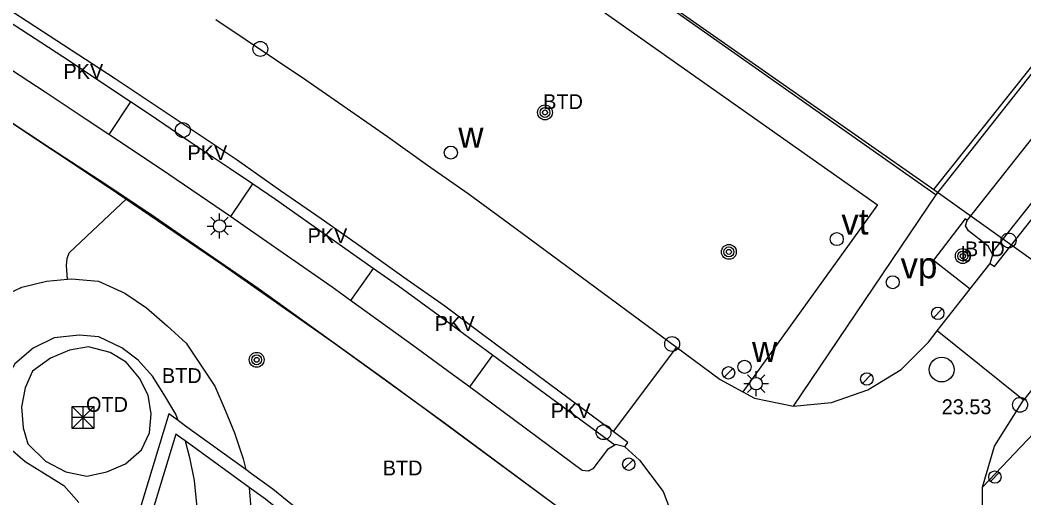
# Model space of a CAD drawing. Extents: x 198240 to 198429, y 356553 to 356721.
# Drawn here: x 198349.04 to 198389.56, y 356639.08 to 356658.34 of the extents above; entities that cross this region are included whole.
import ezdxf

# ---------------------------------------------------------------- set-up
doc = ezdxf.new("R2010")
doc.units = 0
for name, color, linetype in [('Afsluitpaal', 7, 'Continuous'), ('begroeid terreindeel kenmerkpunt', 7, 'Continuous'), ('Benzineput_olieput', 7, 'Continuous'), ('BOOM', 7, 'Continuous'), ('cultuurscheiding geen IMGeo', 7, 'Continuous'), ('grens individueel parkeervak', 7, 'Continuous'), ('Grens maaiveld', 7, 'Continuous'), ('heg geen IMGeo', 7, 'Continuous'), ('Hoogtepunt', 7, 'Continuous'), ('identificerend kenmerkpunt parkeervak', 7, 'Continuous'), ('Inspectieput_rioolput', 7, 'Continuous'), ('kant verharding', 7, 'Continuous'), ('kolk', 7, 'Continuous'), ('LICHTMAST', 7, 'Continuous'), ('onbegroeid terreindeel kenmerkpunt', 7, 'Continuous'), ('perceelsgrens_definitief', 7, 'Continuous'), ('Speelvoorziening', 7, 'Continuous'), ('Verklikker transportleiding', 7, 'Continuous'), ('vlakafsluiter', 7, 'Continuous'), ('waterleidingput', 7, 'Continuous'), ('weginrichtingselement', 7, 'Continuous'), ('weginrichtingselement lijn', 7, 'Continuous')]:
    doc.layers.add(name, color=color, linetype=linetype)

msp = doc.modelspace()

# ---------------------------------------------------------------- linework, layer by layer
at = {"layer": 'Afsluitpaal'}
for p, q in [((198386.253, 356646.699), (198385.903, 356646.342)), ((198377.809, 356644.299), (198377.459, 356643.942)), ((198383.391, 356644.049), (198383.041, 356643.692)), ((198373.781, 356640.617), (198373.431, 356640.26)), ((198388.561, 356640.097), (198388.211, 356639.74))]:
    msp.add_line(p, q, dxfattribs=at)
for centre in [(198386.08, 356646.519), (198377.636, 356644.119), (198383.218, 356643.869), (198373.608, 356640.437), (198388.388, 356639.917)]:
    msp.add_circle(centre, 0.25, dxfattribs=at)
at = {"layer": 'Benzineput_olieput'}
msp.add_circle((198384.261, 356647.771), 0.263, dxfattribs=at)
msp.add_circle((198384.261, 356647.771), 0.263, dxfattribs=at)
at = {"layer": 'BOOM'}
for centre, radius in [((198370.229, 356654.619), 0.3), ((198370.229, 356654.619), 0.2), ((198370.229, 356654.619), 0.1), ((198377.651, 356648.996), 0.3), ((198377.651, 356648.996), 0.2), ((198377.651, 356648.996), 0.1), ((198387.091, 356648.827), 0.3), ((198387.091, 356648.827), 0.2), ((198387.091, 356648.827), 0.1), ((198358.592, 356644.644), 0.3), ((198358.592, 356644.644), 0.2), ((198358.592, 356644.644), 0.1)]:
    msp.add_circle(centre, radius, dxfattribs=at)
at = {"layer": 'cultuurscheiding geen IMGeo'}
msp.add_lwpolyline([(198349.362, 356641.262), (198350.072, 356640.553), (198350.887, 356640.13), (198351.744, 356639.959), (198352.552, 356640.124), (198353.299, 356640.446), (198353.945, 356641.014), (198354.262, 356641.702), (198354.336, 356642.469), (198354.214, 356643.222), (198353.859, 356643.908), (198353.327, 356644.551), (198352.681, 356644.933), (198351.806, 356645.169), (198351.039, 356645.03), (198350.27, 356644.717), (198349.542, 356644.191), (198349.252, 356643.515), (198349.096, 356642.75), (198349.164, 356641.9), (198349.362, 356641.262)], dxfattribs=at)
at = {"layer": 'grens individueel parkeervak'}
for p, q in [((198353.497, 356655.053), (198352.624, 356653.732)), ((198358.424, 356651.737), (198357.53, 356650.42)), ((198363.297, 356648.326), (198362.385, 356647.033)), ((198368.112, 356644.829), (198367.176, 356643.555))]:
    msp.add_line(p, q, dxfattribs=at)
at = {"layer": 'Grens maaiveld'}
for p, q in [((198389.546, 356643.023), (198386.058, 356645.809)), ((198375.533, 356645.157), (198372.981, 356641.75)), ((198355.726, 356641.973), (198355.423, 356642.194)), ((198358.152, 356640.215), (198355.726, 356641.973)), ((198355.703, 356641.372), (198355.432, 356641.569)), ((198358.285, 356639.502), (198355.703, 356641.372)), ((198358.39, 356640.042), (198358.152, 356640.215))]:
    msp.add_line(p, q, dxfattribs=at)
for points in [[(198372.981, 356641.75), (198367.706, 356645.661), (198366.187, 356646.802), (198364.538, 356647.958), (198362.833, 356649.176), (198361.195, 356650.33), (198359.548, 356651.463), (198357.799, 356652.691), (198352.878, 356655.977), (198347.848, 356659.26), (198346.187, 356660.353), (198344.459, 356661.463), (198342.759, 356662.483), (198340.988, 356663.592), (198339.269, 356664.603), (198335.834, 356666.664), (198332.346, 356668.725), (198327.175, 356671.678), (198323.573, 356673.677), (198320.05, 356675.592), (198317.553, 356676.932)], [(198388.2, 356648.534), (198388.372, 356648.404), (198394.89, 356656.659), (198396.809, 356659.133), (198396.637, 356659.256)], [(198349.119, 356647.571), (198350.115, 356647.818), (198350.964, 356647.896)], [(198350.964, 356647.896), (198351.115, 356647.91), (198352.21, 356647.812), (198353.267, 356647.331), (198354.149, 356646.74), (198354.975, 356646.017), (198355.744, 356645.322), (198356.902, 356643.575), (198357.326, 356642.62), (198357.697, 356641.7), (198358.046, 356640.645), (198358.152, 356640.215)], [(198347.617, 356639.006), (198347.475, 356639.042), (198346.828, 356639.275), (198346.287, 356639.639), (198345.935, 356640.096), (198345.691, 356640.614), (198345.65, 356641.176), (198345.843, 356643.252), (198346.007, 356643.901), (198346.27, 356644.596), (198346.627, 356645.198), (198347.603, 356646.563), (198348.274, 356647.167), (198349.119, 356647.571)], [(198355.423, 356642.194), (198355.328, 356642.451), (198354.846, 356643.261), (198354.393, 356643.982), (198353.807, 356644.635), (198353.149, 356645.122), (198352.227, 356645.566), (198351.429, 356645.638), (198350.422, 356645.527), (198349.57, 356645.114), (198348.838, 356644.484), (198348.416, 356643.729), (198348.214, 356642.804), (198348.101, 356641.911), (198348.543, 356641.156), (198349.256, 356640.546), (198350.809, 356639.574), (198351.421, 356638.896)], [(198349.362, 356641.262), (198350.072, 356640.553), (198350.887, 356640.13), (198351.744, 356639.959), (198352.552, 356640.124), (198353.299, 356640.446), (198353.945, 356641.014), (198354.262, 356641.702), (198354.336, 356642.469), (198354.214, 356643.222), (198353.859, 356643.908), (198353.327, 356644.551), (198352.681, 356644.933), (198351.806, 356645.169), (198351.039, 356645.03), (198350.27, 356644.717), (198349.542, 356644.191), (198349.252, 356643.515), (198349.096, 356642.75), (198349.164, 356641.9), (198349.362, 356641.262)], [(198355.423, 356642.194), (198355.054, 356642.463), (198353.086, 356636)], [(198355.432, 356641.569), (198355.328, 356641.645), (198353.564, 356635.854)], [(198373.454, 356641.134), (198373.573, 356641.311), (198372.981, 356641.75)], [(198355.703, 356641.372), (198355.885, 356640.7), (198356.064, 356639.773), (198356.166, 356638.829), (198356.197, 356637.88), (198356.155, 356637.553)], [(198360.838, 356638.137), (198359.247, 356639.427), (198358.39, 356640.042)], [(198358.285, 356639.502), (198358.345, 356638.809), (198358.369, 356637.843), (198358.247, 356636.985), (198358.109, 356636.322)], [(198360.315, 356637.918), (198358.943, 356639.029), (198358.285, 356639.502)]]:
    msp.add_lwpolyline(points, dxfattribs=at)
at = {"layer": 'heg geen IMGeo'}
for points in [[(198360.838, 356638.137), (198359.247, 356639.427), (198358.39, 356640.042)], [(198360.315, 356637.918), (198358.943, 356639.029), (198358.285, 356639.502)]]:
    msp.add_lwpolyline(points, dxfattribs=at)
at = {"layer": 'Inspectieput_rioolput'}
msp.add_circle((198386.24, 356644.252), 0.5, dxfattribs=at)
at = {"layer": 'kant verharding'}
for p, q in [((198387.265, 356650.262), (198391.017, 356655.011)), ((198392.286, 356654.04), (198388.264, 356648.959)), ((198353.348, 356651.154), (198352.51, 356651.714)), ((198387.388, 356647.501), (198388.2, 356648.534)), ((198386.058, 356645.809), (198387.388, 356647.501)), ((198373.044, 356641.207), (198368.112, 356644.829))]:
    msp.add_line(p, q, dxfattribs=at)
for points in [[(198352.51, 356651.714), (198350.276, 356653.164), (198348.4, 356654.399), (198343.742, 356657.419), (198341.543, 356658.825), (198339.43, 356660.09), (198337.442, 356661.338), (198333.99, 356663.38), (198332.34, 356664.377), (198330.533, 356665.43), (198328.787, 356666.422), (198324.464, 356668.899), (198322.677, 356669.861), (198318.431, 356672.186), (198316.529, 356673.188), (198314.814, 356674.063)], [(198360.197, 356669.267), (198362.576, 356667.673), (198364.582, 356666.298), (198366.655, 356664.862), (198368.765, 356663.429), (198386.018, 356651.295)], [(198361.758, 356666.189), (198372.084, 356659.041), (198383.655, 356650.892), (198378.215, 356643.352)], [(198404.26, 356661.992), (198403.096, 356660.379), (198401.903, 356658.745), (198399.503, 356655.567), (198397.022, 356652.414), (198395.783, 356650.82), (198394.543, 356649.264), (198393.305, 356647.686), (198392.04, 356646.144), (198390.785, 356644.559), (198389.546, 356643.023)], [(198353.497, 356655.053), (198352.664, 356655.604), (198351.039, 356656.691), (198348.537, 356658.312)], [(198356.948, 356658.373), (198360.581, 356655.932), (198363.871, 356653.655), (198365.49, 356652.496), (198367.13, 356651.344), (198368.743, 356650.174), (198375.533, 356645.157)], [(198386.018, 356651.295), (198391.518, 356658.255)], [(198352.624, 356653.732), (198351.715, 356654.33), (198350.052, 356655.44), (198347.676, 356656.983)], [(198358.424, 356651.737), (198357.528, 356652.345), (198355.914, 356653.42), (198354.291, 356654.528), (198353.497, 356655.053)], [(198357.53, 356650.42), (198355.048, 356652.112), (198353.386, 356653.231), (198352.624, 356653.732)], [(198363.297, 356648.326), (198359.359, 356651.103), (198358.424, 356651.737)], [(198350.964, 356647.896), (198350.918, 356648.442), (198350.938, 356648.733), (198351.026, 356648.955), (198353.348, 356651.154)], [(198355.686, 356649.56), (198354.494, 356650.389), (198353.348, 356651.154)], [(198362.385, 356647.033), (198361.638, 356647.571), (198358.345, 356649.864), (198357.53, 356650.42)], [(198387.265, 356650.262), (198387.19, 356650.335), (198385.905, 356648.667), (198387.388, 356647.501)], [(198388.264, 356648.959), (198388.115, 356649.222), (198387.326, 356649.845), (198387.2, 356650.042), (198387.265, 356650.262)], [(198375.379, 356635.292), (198365.453, 356642.617), (198363.834, 356643.796), (198358.657, 356647.515), (198356.63, 356648.904), (198355.686, 356649.56)], [(198388.2, 356648.534), (198388.305, 356648.886), (198388.264, 356648.959)], [(198368.112, 356644.829), (198367.455, 356645.312), (198365.923, 356646.447), (198364.312, 356647.61), (198363.297, 356648.326)], [(198367.176, 356643.555), (198366.501, 356644.056), (198364.878, 356645.238), (198362.385, 356647.033)], [(198380.26, 356642.781), (198381.79, 356642.926), (198383.261, 356643.431), (198384.604, 356644.253), (198385.706, 356645.36), (198386.058, 356645.809)], [(198375.533, 356645.157), (198377.297, 356643.856), (198378.215, 356643.352)], [(198373.044, 356641.207), (198372.758, 356641.034), (198372.158, 356640.244), (198371.972, 356640.158), (198371.735, 356640.175), (198367.176, 356643.555)], [(198378.215, 356643.352), (198378.686, 356643.094), (198380.26, 356642.781)], [(198387.884, 356639.508), (198388.368, 356641.168), (198389.546, 356643.023)], [(198373.454, 356641.134), (198373.075, 356641.226), (198373.044, 356641.207)], [(198373.454, 356641.134), (198374.046, 356640.603), (198374.994, 356639.335), (198375.554, 356637.877), (198375.659, 356636.295), (198375.379, 356635.292)], [(198388.921, 356635.368), (198388.706, 356635.6), (198387.879, 356637.792), (198387.884, 356639.508)]]:
    msp.add_lwpolyline(points, dxfattribs=at)
at = {"layer": 'kolk'}
for centre in [(198358.742, 356657.18), (198355.613, 356653.907), (198388.94, 356649.457), (198375.361, 356645.283), (198389.403, 356642.831), (198372.591, 356641.725)]:
    msp.add_circle(centre, 0.3, dxfattribs=at)
at = {"layer": 'LICHTMAST'}
for p, q in [((198357.094, 356650.289), (198357.094, 356650.539)), ((198356.594, 356650.039), (198356.844, 356650.039)), ((198356.917, 356650.216), (198356.74, 356650.393)), ((198357.271, 356650.216), (198357.448, 356650.393)), ((198357.344, 356650.039), (198357.594, 356650.039)), ((198356.74, 356649.685), (198356.917, 356649.862)), ((198357.094, 356649.539), (198357.094, 356649.789)), ((198357.448, 356649.685), (198357.271, 356649.862)), ((198378.573, 356643.86), (198378.396, 356644.037)), ((198378.75, 356643.933), (198378.75, 356644.183)), ((198378.927, 356643.86), (198379.104, 356644.037)), ((198378.25, 356643.683), (198378.5, 356643.683)), ((198379, 356643.683), (198379.25, 356643.683)), ((198378.396, 356643.329), (198378.573, 356643.506)), ((198378.75, 356643.183), (198378.75, 356643.433)), ((198379.104, 356643.329), (198378.927, 356643.506))]:
    msp.add_line(p, q, dxfattribs=at)
for centre in [(198357.094, 356650.039), (198378.75, 356643.683)]:
    msp.add_circle(centre, 0.25, dxfattribs=at)
at = {"layer": 'perceelsgrens_definitief'}
for points in [[(198370.586, 356638.823), (198366.164, 356642.103), (198361.698, 356645.323), (198357.189, 356648.483), (198352.638, 356651.581), (198348.046, 356654.619), (198343.413, 356657.594), (198338.741, 356660.506), (198334.03, 356663.356), (198329.281, 356666.142), (198324.495, 356668.863), (198319.673, 356671.52), (198314.815, 356674.112)], [(198370.943, 356661.977), (198385.92, 356651.508)], [(198385.92, 356651.508), (198392.722, 356660.05)], [(198385.92, 356651.508), (198394.046, 356645.723)]]:
    msp.add_lwpolyline(points, dxfattribs=at)
at = {"layer": 'Speelvoorziening'}
for p, q in [((198351.141, 356642.756), (198352.021, 356642.756)), ((198351.141, 356641.876), (198351.141, 356642.756)), ((198351.141, 356642.756), (198352.021, 356641.876)), ((198351.141, 356641.876), (198352.021, 356642.756)), ((198351.581, 356642.756), (198351.581, 356641.876)), ((198352.021, 356642.756), (198352.021, 356641.876)), ((198352.021, 356642.316), (198351.141, 356642.316)), ((198352.021, 356641.876), (198351.141, 356641.876))]:
    msp.add_line(p, q, dxfattribs=at)
at = {"layer": 'Verklikker transportleiding'}
msp.add_circle((198382.004, 356649.51), 0.263, dxfattribs=at)
at = {"layer": 'vlakafsluiter'}
for p, q in [((198380.26, 356642.781), (198386.018, 356651.295)), ((198387.884, 356639.508), (198393.74, 356645.683))]:
    msp.add_line(p, q, dxfattribs=at)
at = {"layer": 'waterleidingput'}
for centre in [(198366.429, 356652.999), (198366.429, 356652.999), (198378.281, 356644.362), (198378.281, 356644.362)]:
    msp.add_circle(centre, 0.263, dxfattribs=at)
at = {"layer": 'weginrichtingselement lijn'}
for points in [[(198372.981, 356641.75), (198367.706, 356645.661), (198366.187, 356646.802), (198364.538, 356647.958), (198362.833, 356649.176), (198361.195, 356650.33), (198359.548, 356651.463), (198357.799, 356652.691), (198352.878, 356655.977), (198347.848, 356659.26), (198346.187, 356660.353), (198344.459, 356661.463), (198342.759, 356662.483), (198340.988, 356663.592), (198339.269, 356664.603), (198335.834, 356666.664), (198332.346, 356668.725), (198327.175, 356671.678), (198323.573, 356673.677), (198320.05, 356675.592), (198317.553, 356676.932)], [(198388.2, 356648.534), (198388.372, 356648.404), (198394.89, 356656.659), (198396.809, 356659.133), (198396.637, 356659.256)], [(198373.454, 356641.134), (198373.573, 356641.311), (198372.981, 356641.75)]]:
    msp.add_lwpolyline(points, dxfattribs=at)

# ---------------------------------------------------------------- texts
at = {"layer": 'begroeid terreindeel kenmerkpunt'}
for p in [(198370.154, 356654.753), (198387.178, 356648.816), (198354.77, 356643.708), (198363.68, 356639.983)]:
    msp.add_text('BTD', height=0.6, dxfattribs=at).set_placement(p)
at = {"layer": 'Benzineput_olieput'}
msp.add_text('vp', height=1.05, dxfattribs=at).set_placement((198384.581, 356647.932))
at = {"layer": 'Hoogtepunt'}
msp.add_text('23.53', height=0.6, dxfattribs=at).set_placement((198386.24, 356642.452))
msp.add_text('23.53', height=0.6, dxfattribs=at).set_placement((198386.24, 356642.452))
at = {"layer": 'identificerend kenmerkpunt parkeervak'}
for p in [(198350.795, 356655.974), (198355.8, 356652.698), (198360.647, 356649.35), (198365.784, 356645.807), (198370.466, 356642.292)]:
    msp.add_text('PKV', height=0.6, dxfattribs=at).set_placement(p)
at = {"layer": 'onbegroeid terreindeel kenmerkpunt'}
msp.add_text('OTD', height=0.6, dxfattribs=at).set_placement((198351.704, 356642.545))
at = {"layer": 'Verklikker transportleiding'}
msp.add_text('vt', height=1.05, dxfattribs=at).set_placement((198382.19, 356649.696))
at = {"layer": 'waterleidingput'}
for p in [(198366.733, 356653.197), (198378.585, 356644.56)]:
    msp.add_text('w', height=1.05, dxfattribs=at).set_placement(p)
at = {"layer": 'weginrichtingselement'}
msp.add_text('b', height=0.6, rotation=0.2905, dxfattribs=at).set_placement((198387.015, 356648.605))

doc.saveas('drawing.dxf')
